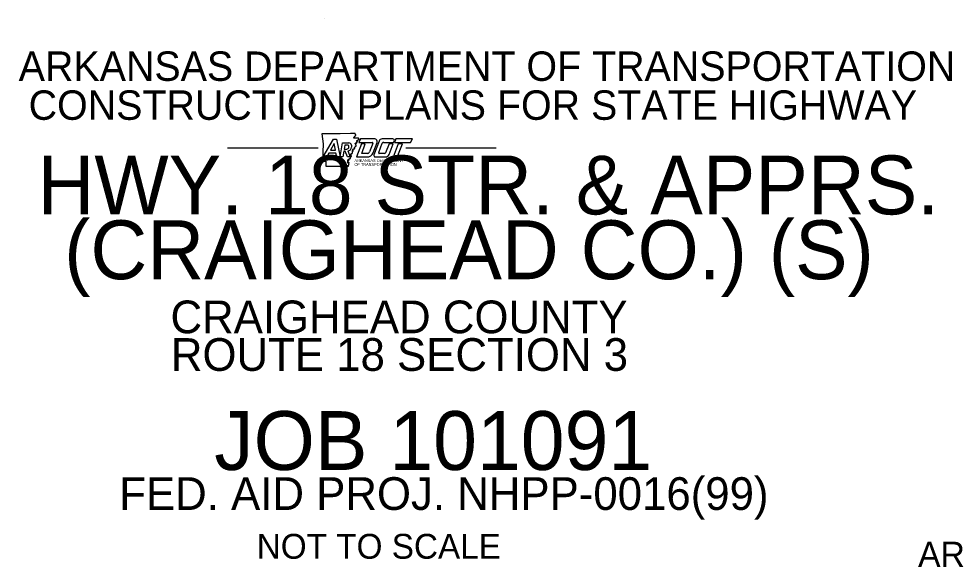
# Model space of a CAD drawing. Extents: x -28335 to 1228743, y -22428 to 152440.
# Drawn here: x -5314 to 23831, y 4514 to 21584 of the extents above; entities that cross this region are included whole.
import ezdxf

# ---------------------------------------------------------------- set-up
doc = ezdxf.new("R2010")
doc.units = 0
for name, color, linetype in [('2', 7, 'Continuous'), ('20', 7, 'Continuous'), ('58', 7, 'Continuous'), ('8', 7, 'Continuous'), ('Default', 7, 'Continuous')]:
    doc.layers.add(name, color=color, linetype=linetype)

msp = doc.modelspace()

# ---------------------------------------------------------------- linework, layer by layer
at = {"layer": '2'}
msp.add_line((4189, 21584), (4189, 21584), dxfattribs=at)
msp.add_line((4189, 21584), (4189, 21584), dxfattribs=at)
at = {"layer": '20'}
for p, q in [((4153, 17284), (4467, 17840)), ((4467, 17840), (4562, 17840)), ((4562, 17840), (4676, 17291)), ((5241, 17870), (5098, 17863)), ((5308, 17842), (5261, 17737)), ((5755, 17842), (5308, 17842)), ((6320, 17842), (5987, 17842)), ((6346, 17746), (6360, 17785)), ((6407, 17845), (6364, 17733)), ((6924, 17844), (6407, 17845)), ((6860, 17733), (6924, 17844)), ((4492, 17697), (4377, 17494)), ((4377, 17494), (4531, 17494)), ((4531, 17494), (4492, 17697)), ((4676, 17291), (4754, 17721)), ((4754, 17721), (4952, 17721)), ((4822, 17650), (4802, 17525)), ((4802, 17525), (4882, 17525)), ((4910, 17650), (4822, 17650)), ((4950, 17594), (4950, 17610)), ((5034, 17650), (5034, 17588)), ((5261, 17737), (5667, 17737)), ((5460, 17690), (5340, 17690)), ((5350, 17394), (5460, 17690)), ((5689, 17705), (5588, 17440)), ((5699, 17409), (5827, 17737)), ((5888, 17773), (5726, 17352)), ((5876, 17420), (5989, 17713)), ((6023, 17737), (6333, 17737)), ((6202, 17690), (6085, 17410)), ((6197, 17362), (6323, 17690)), ((6323, 17690), (6202, 17690)), ((6485, 17691), (6327, 17280)), ((6364, 17733), (6860, 17733)), ((6449, 17280), (6612, 17691)), ((6612, 17691), (6485, 17691)), ((4262, 17284), (4153, 17284)), ((4547, 17404), (4324, 17404)), ((4571, 17282), (4547, 17404)), ((4675, 17282), (4571, 17282)), ((4759, 17282), (4675, 17282)), ((4790, 17461), (4759, 17282)), ((4832, 17461), (4790, 17461)), ((4901, 17282), (4832, 17461)), ((4994, 17282), (4901, 17282)), ((4916, 17470), (4994, 17282)), ((5517, 17392), (5352, 17392)), ((5774, 17282), (6080, 17282)), ((6058, 17392), (5892, 17392)), ((6327, 17280), (6449, 17280))]:
    msp.add_line(p, q, dxfattribs=at)
for points in [[(5143, 18010), (4997, 18007), (4681, 18002), (4414, 18001), (4110, 18002)], [(4110, 18002), (4149, 17688), (4132, 17177)], [(5340, 17690), (5183, 17282), (5515, 17282)], [(4324, 17404), (4262, 17284), (4262, 17283), (4262, 17284)], [(4236, 17147), (4236, 16995), (4926, 16993)]]:
    msp.add_lwpolyline(points, dxfattribs=at)
for centre, radius, start, end in [((5755, 17765), 77, 338.81, 90.0244), ((5987, 17735), 107, 90.0159, 159.0252), ((6320, 17799), 42.5, 339.9797, 90.0159), ((4882, 17593), 68.4, 270, 0.8203), ((4910, 17610), 40, 0, 90.2531), ((4906, 17598), 128, 274.233, 355.6275), ((4942, 17627), 94.7, 14.1904, 83.9934), ((5667, 17714), 23.5, 339.1692, 89.9954), ((6023, 17700), 37.2, 90.0183, 159.0781), ((6333, 17750), 13.1, 270.0183, 339.9797), ((5352, 17394), 1.77, 159.6445, 270.0081), ((5515, 17480), 198, 269.9471, 338.81), ((5517, 17467), 75.1, 270.0081, 339.1692), ((5774, 17334), 51.6, 159.0252, 269.9823), ((5891, 17410), 18, 146.4856, 270.228), ((6058, 17421), 29.4, 270.0618, 337.3322), ((6080, 17407), 125, 269.9823, 339.0187)]:
    msp.add_arc(centre, radius, start, end, dxfattribs=at)
for points in [[(5098, 17863), (5103, 17875), (5104, 17880), (5108, 17886), (5110, 17891), (5115, 17896), (5118, 17900), (5122, 17904), (5124, 17910), (5128, 17915), (5132, 17919), (5137, 17924), (5142, 17929), (5145, 17933), (5149, 17937), (5153, 17940), (5158, 17945), (5159, 17951), (5160, 17957), (5160, 17964), (5161, 17971), (5160, 17977), (5156, 17983), (5150, 17986), (5147, 17990), (5146, 17998), (5144, 18002), (5143, 18010)], [(5065, 17452), (5064, 17453), (5059, 17458), (5059, 17466), (5059, 17472), (5060, 17478), (5063, 17482), (5066, 17478), (5068, 17474), (5069, 17469), (5073, 17467), (5078, 17468), (5081, 17473), (5083, 17478), (5083, 17483), (5081, 17487), (5076, 17488), (5070, 17489), (5067, 17492), (5069, 17500), (5069, 17505), (5069, 17511), (5073, 17513), (5075, 17510), (5074, 17505), (5074, 17500), (5081, 17497), (5085, 17502)], [(5085, 17502), (5086, 17511), (5087, 17516), (5086, 17525), (5084, 17531), (5084, 17537), (5088, 17539), (5092, 17538), (5096, 17535), (5100, 17530), (5104, 17529), (5108, 17531), (5112, 17531), (5117, 17531), (5121, 17530), (5124, 17532), (5126, 17536), (5127, 17542), (5131, 17545), (5133, 17550), (5134, 17556), (5133, 17561), (5130, 17567), (5126, 17572), (5126, 17579), (5129, 17583), (5135, 17584), (5136, 17585)], [(5136, 17585), (5141, 17585), (5145, 17591), (5147, 17596), (5149, 17600), (5152, 17606), (5154, 17611), (5158, 17615), (5163, 17614), (5168, 17613), (5172, 17614), (5175, 17620), (5174, 17625), (5172, 17631), (5171, 17636), (5170, 17644), (5167, 17647), (5161, 17650), (5156, 17655), (5152, 17659), (5158, 17663), (5164, 17666), (5163, 17672), (5164, 17678), (5168, 17684), (5167, 17689)], [(4915, 17188), (4917, 17192), (4921, 17193), (4927, 17191), (4933, 17188), (4938, 17184), (4945, 17181), (4950, 17184), (4954, 17189), (4952, 17196), (4946, 17197), (4941, 17197), (4935, 17203), (4935, 17212), (4939, 17213), (4945, 17216), (4949, 17217), (4954, 17215), (4961, 17213), (4964, 17215), (4969, 17222), (4970, 17228), (4971, 17233), (4986, 17232), (4995, 17237), (4995, 17247), (4996, 17254)], [(4996, 17254), (4998, 17260), (4998, 17265), (4999, 17267), (5000, 17272), (5005, 17274), (5011, 17282), (5012, 17294), (5030, 17299), (5031, 17307), (5032, 17313), (5026, 17320), (5019, 17323), (5012, 17338), (5013, 17353), (5008, 17362), (5012, 17364), (5013, 17364)], [(5013, 17364), (5018, 17364), (5024, 17368), (5024, 17369), (5025, 17375), (5024, 17380), (5022, 17387), (5023, 17390), (5027, 17390), (5032, 17388), (5033, 17385), (5033, 17382), (5034, 17379), (5036, 17377), (5039, 17377), (5043, 17382), (5044, 17386), (5045, 17392), (5048, 17395), (5051, 17397), (5056, 17402), (5058, 17407), (5060, 17415), (5059, 17423), (5061, 17430), (5062, 17436), (5066, 17442), (5067, 17447), (5065, 17452)], [(4132, 17177), (4137, 17170), (4139, 17165), (4143, 17159), (4147, 17156), (4153, 17155), (4154, 17149), (4159, 17148), (4164, 17150), (4170, 17148), (4177, 17152), (4181, 17151), (4186, 17154), (4190, 17150), (4197, 17153), (4204, 17157), (4210, 17153), (4216, 17153), (4222, 17152), (4228, 17152), (4233, 17149), (4236, 17147)], [(4947, 17117), (4946, 17116), (4943, 17113), (4941, 17110), (4938, 17107), (4936, 17104), (4931, 17102), (4924, 17101), (4921, 17103), (4920, 17108), (4924, 17112), (4929, 17114), (4933, 17116), (4936, 17121), (4934, 17127), (4929, 17130), (4925, 17127), (4923, 17123), (4921, 17120), (4917, 17118), (4914, 17117), (4912, 17119), (4912, 17124), (4915, 17131), (4917, 17136), (4917, 17141), (4915, 17149), (4913, 17155), (4914, 17156), (4918, 17158), (4924, 17160), (4927, 17161), (4928, 17166), (4924, 17172), (4919, 17177), (4916, 17184), (4915, 17188)], [(4926, 16993), (4934, 16997), (4937, 17001), (4937, 17004), (4935, 17009), (4931, 17014), (4928, 17016), (4924, 17021), (4923, 17027), (4927, 17030), (4934, 17029), (4941, 17029), (4944, 17031), (4945, 17036), (4945, 17040), (4945, 17045), (4947, 17052), (4950, 17057), (4954, 17062), (4954, 17067), (4951, 17070), (4946, 17069), (4942, 17068), (4939, 17073), (4937, 17078), (4936, 17086), (4941, 17093), (4945, 17097), (4949, 17102), (4951, 17108), (4952, 17114), (4950, 17117), (4947, 17117)]]:
    msp.add_spline(points, degree=3, dxfattribs=at)
for points in [[(5199, 17777), (5199, 17777), (5199, 17777), (5199, 17778), (5199, 17778), (5200, 17779), (5200, 17780), (5200, 17780), (5200, 17781), (5200, 17781), (5200, 17782), (5200, 17783), (5200, 17783), (5200, 17784), (5199, 17784), (5199, 17785), (5199, 17785), (5199, 17786), (5199, 17787), (5199, 17787), (5199, 17788), (5199, 17788), (5199, 17789), (5199, 17789), (5199, 17790), (5199, 17790), (5200, 17791), (5200, 17791), (5200, 17792), (5201, 17793), (5202, 17793), (5202, 17794), (5202, 17794), (5202, 17794), (5202, 17794), (5203, 17794), (5203, 17794), (5203, 17795), (5204, 17795), (5204, 17795), (5205, 17795), (5205, 17796), (5206, 17796), (5206, 17796), (5207, 17796), (5208, 17796), (5209, 17796), (5209, 17797), (5210, 17797), (5211, 17797), (5212, 17797), (5213, 17797), (5214, 17797), (5214, 17797), (5215, 17797), (5215, 17797), (5216, 17797), (5216, 17797), (5217, 17798), (5217, 17798), (5217, 17798), (5218, 17798), (5218, 17798), (5219, 17798), (5220, 17798), (5221, 17798), (5222, 17799), (5223, 17799), (5224, 17799), (5225, 17800), (5226, 17800), (5227, 17800), (5228, 17800), (5229, 17801), (5230, 17801), (5231, 17801), (5231, 17802), (5231, 17802), (5231, 17802), (5232, 17803), (5232, 17803), (5232, 17803), (5232, 17804), (5232, 17804), (5232, 17805), (5233, 17805), (5233, 17805), (5233, 17806), (5233, 17806), (5234, 17806), (5234, 17807)], [(5234, 17807), (5234, 17807), (5234, 17807), (5234, 17807), (5235, 17807), (5235, 17808), (5235, 17808), (5236, 17809), (5236, 17809), (5237, 17809), (5237, 17810), (5238, 17810), (5238, 17810), (5239, 17811), (5239, 17811), (5240, 17811), (5240, 17811), (5241, 17811), (5241, 17811), (5242, 17812), (5242, 17812), (5243, 17812), (5243, 17812), (5244, 17812), (5244, 17812), (5245, 17813), (5246, 17813), (5247, 17814), (5248, 17814), (5249, 17815), (5250, 17815), (5251, 17815), (5251, 17816), (5251, 17816), (5252, 17817), (5252, 17817), (5252, 17817), (5253, 17818), (5253, 17819), (5253, 17820), (5253, 17820), (5253, 17821), (5253, 17821), (5253, 17822), (5253, 17822), (5253, 17823), (5253, 17823), (5253, 17824), (5253, 17824), (5252, 17824), (5252, 17825), (5252, 17825), (5251, 17826), (5251, 17826), (5250, 17827), (5250, 17827), (5250, 17827), (5249, 17828), (5249, 17828), (5248, 17828), (5248, 17829), (5247, 17829), (5247, 17829), (5246, 17830), (5245, 17831), (5245, 17832), (5244, 17832), (5243, 17833), (5243, 17833), (5243, 17834), (5242, 17834), (5242, 17834), (5242, 17835), (5242, 17835), (5242, 17835), (5242, 17835), (5242, 17835), (5242, 17835), (5242, 17835), (5242, 17836), (5242, 17836), (5242, 17836), (5243, 17836), (5243, 17837), (5244, 17837), (5244, 17837), (5245, 17838), (5245, 17838), (5246, 17838), (5246, 17838), (5247, 17839), (5247, 17839), (5247, 17839), (5247, 17839), (5248, 17839), (5248, 17839), (5248, 17839), (5249, 17839), (5249, 17839), (5250, 17839), (5250, 17839), (5250, 17839), (5251, 17838), (5251, 17838), (5251, 17838), (5251, 17838)], [(5251, 17838), (5251, 17838), (5252, 17838), (5252, 17838), (5253, 17839), (5254, 17839), (5255, 17839), (5256, 17839), (5257, 17839), (5258, 17839), (5258, 17839), (5259, 17839), (5259, 17839), (5259, 17839), (5259, 17839), (5259, 17839), (5260, 17839), (5260, 17839), (5261, 17839), (5261, 17839), (5262, 17839), (5262, 17839), (5263, 17839), (5263, 17840), (5263, 17840), (5264, 17840), (5264, 17840), (5264, 17840), (5264, 17840), (5264, 17840), (5264, 17840), (5264, 17840), (5264, 17841), (5264, 17841), (5264, 17841), (5265, 17841), (5265, 17842), (5265, 17842), (5265, 17842), (5265, 17843), (5265, 17843), (5265, 17844), (5265, 17844), (5264, 17846), (5263, 17847), (5262, 17849), (5261, 17850), (5260, 17852), (5259, 17853), (5258, 17853), (5258, 17854), (5258, 17854), (5257, 17854), (5257, 17854), (5256, 17854), (5256, 17854), (5255, 17854), (5255, 17854), (5255, 17854), (5254, 17854), (5254, 17855), (5252, 17855), (5251, 17856), (5250, 17858), (5250, 17858), (5249, 17859), (5249, 17859), (5249, 17860), (5249, 17860), (5248, 17861), (5248, 17861), (5248, 17862), (5248, 17862), (5247, 17863), (5247, 17863), (5247, 17864), (5247, 17864), (5246, 17864), (5246, 17865), (5246, 17865), (5246, 17865), (5246, 17866), (5245, 17866), (5245, 17867), (5244, 17868), (5244, 17868), (5243, 17869), (5243, 17869), (5242, 17870), (5241, 17870), (5241, 17870)], [(5167, 17689), (5166, 17690), (5166, 17691), (5166, 17692), (5165, 17693), (5165, 17693), (5165, 17693), (5165, 17694), (5164, 17694), (5164, 17694), (5164, 17694), (5164, 17695), (5164, 17695), (5164, 17695), (5163, 17695), (5163, 17695), (5163, 17695), (5162, 17695), (5162, 17695), (5162, 17695), (5162, 17695), (5161, 17695), (5161, 17695), (5161, 17695), (5161, 17694), (5160, 17694), (5160, 17694), (5160, 17693), (5160, 17693), (5160, 17693), (5160, 17692), (5160, 17692), (5160, 17692), (5160, 17691), (5159, 17691), (5159, 17691), (5159, 17690), (5159, 17690), (5158, 17690), (5158, 17690), (5158, 17690), (5158, 17690), (5157, 17690), (5157, 17689), (5157, 17689), (5157, 17689), (5156, 17689), (5156, 17689), (5156, 17689), (5155, 17689), (5155, 17689), (5155, 17689), (5154, 17689), (5154, 17689), (5154, 17690), (5153, 17690), (5153, 17690), (5153, 17690), (5152, 17690), (5152, 17690), (5152, 17691), (5151, 17691), (5151, 17691), (5151, 17691), (5151, 17691), (5151, 17691), (5151, 17691), (5151, 17692), (5151, 17692), (5150, 17692), (5150, 17693), (5150, 17693), (5150, 17694), (5149, 17694), (5149, 17695), (5149, 17695), (5149, 17696), (5150, 17696), (5150, 17697), (5150, 17697), (5150, 17697), (5150, 17698), (5151, 17698), (5151, 17699), (5151, 17699), (5152, 17700), (5152, 17701), (5153, 17701), (5153, 17702), (5154, 17702), (5154, 17703), (5155, 17703), (5155, 17703), (5156, 17704), (5156, 17704), (5157, 17705), (5157, 17705), (5158, 17705), (5158, 17706), (5159, 17706), (5159, 17707), (5160, 17707), (5161, 17708), (5161, 17709), (5162, 17710), (5163, 17710), (5163, 17711), (5164, 17711), (5165, 17712), (5165, 17712), (5165, 17712), (5166, 17713), (5166, 17713), (5166, 17713), (5167, 17713), (5167, 17714), (5168, 17714), (5168, 17714)], [(5168, 17714), (5168, 17714), (5168, 17714), (5168, 17714), (5169, 17714), (5169, 17713), (5170, 17713), (5170, 17713), (5170, 17713), (5171, 17712), (5171, 17712), (5171, 17712), (5171, 17711), (5172, 17711), (5172, 17711), (5172, 17711), (5172, 17710), (5172, 17710), (5172, 17710), (5172, 17709), (5172, 17709), (5172, 17708), (5172, 17708), (5172, 17707), (5173, 17707), (5173, 17706), (5173, 17705), (5173, 17704), (5173, 17703), (5173, 17701), (5173, 17700), (5174, 17699), (5174, 17698), (5174, 17697), (5174, 17696), (5174, 17696), (5175, 17696), (5175, 17696), (5175, 17696), (5175, 17696), (5175, 17696), (5176, 17696), (5176, 17697), (5177, 17697), (5178, 17698), (5178, 17699), (5178, 17699), (5179, 17700), (5179, 17700), (5179, 17701), (5180, 17701), (5180, 17702), (5180, 17702), (5180, 17703), (5181, 17704), (5181, 17704), (5181, 17705), (5181, 17705), (5182, 17707), (5182, 17710), (5183, 17712), (5183, 17713), (5183, 17715), (5183, 17716), (5182, 17718), (5182, 17720), (5181, 17722), (5181, 17724), (5180, 17725), (5180, 17727), (5180, 17727), (5180, 17727), (5180, 17727)], [(5180, 17727), (5180, 17728), (5180, 17728), (5180, 17728), (5180, 17729), (5180, 17729), (5180, 17730), (5181, 17730), (5181, 17731), (5181, 17731), (5181, 17732), (5181, 17732), (5182, 17732), (5182, 17733), (5182, 17733), (5182, 17733), (5182, 17733), (5182, 17734), (5181, 17734), (5181, 17734), (5181, 17735), (5181, 17735), (5181, 17736), (5181, 17736), (5181, 17737), (5181, 17737), (5181, 17737), (5182, 17738), (5182, 17738), (5182, 17738), (5182, 17738), (5182, 17739), (5182, 17739), (5182, 17739), (5183, 17739), (5183, 17740), (5183, 17740), (5184, 17740), (5184, 17740), (5185, 17740), (5185, 17740), (5185, 17740), (5186, 17740), (5187, 17740), (5188, 17739), (5189, 17739), (5191, 17738), (5192, 17738), (5193, 17737), (5194, 17737), (5194, 17737), (5194, 17736), (5195, 17736), (5195, 17735), (5195, 17735), (5195, 17734), (5196, 17734), (5196, 17733), (5196, 17733), (5196, 17733), (5197, 17732), (5198, 17732), (5198, 17732), (5199, 17731), (5200, 17731), (5201, 17731), (5202, 17731), (5203, 17732), (5204, 17732), (5204, 17732), (5205, 17733), (5205, 17733), (5205, 17733), (5206, 17733), (5206, 17733), (5206, 17734), (5206, 17734), (5206, 17734), (5206, 17734), (5207, 17735), (5207, 17737), (5207, 17738), (5206, 17740), (5205, 17741), (5204, 17742), (5204, 17743), (5203, 17743), (5203, 17743), (5203, 17743), (5202, 17744), (5202, 17744), (5202, 17744), (5201, 17744), (5201, 17744), (5201, 17745), (5200, 17745), (5200, 17745)], [(5200, 17745), (5200, 17745), (5200, 17745), (5200, 17745), (5199, 17746), (5199, 17746), (5198, 17747), (5198, 17748), (5198, 17749), (5198, 17749), (5199, 17749), (5199, 17750), (5199, 17750), (5200, 17751), (5200, 17751), (5200, 17751), (5201, 17752), (5202, 17753), (5203, 17753), (5203, 17753), (5204, 17753), (5204, 17754), (5204, 17754), (5205, 17754), (5205, 17754), (5206, 17754), (5206, 17754), (5206, 17754), (5207, 17755), (5207, 17755), (5208, 17755), (5209, 17756), (5211, 17758), (5212, 17759), (5213, 17760), (5213, 17760), (5213, 17760), (5214, 17761), (5214, 17761), (5214, 17762), (5215, 17763), (5216, 17763), (5216, 17764), (5217, 17765), (5217, 17766), (5217, 17766), (5217, 17767), (5217, 17767), (5217, 17768), (5217, 17768), (5217, 17768), (5217, 17769), (5217, 17769), (5216, 17769), (5216, 17769), (5216, 17769), (5216, 17770), (5216, 17770), (5215, 17770), (5215, 17770), (5214, 17770), (5213, 17771), (5212, 17771), (5211, 17771), (5211, 17772), (5210, 17772), (5210, 17772), (5210, 17772), (5209, 17772), (5209, 17772), (5208, 17772), (5208, 17772), (5207, 17772), (5207, 17772), (5206, 17772), (5206, 17772), (5205, 17772), (5205, 17772), (5204, 17772), (5204, 17772), (5203, 17772), (5202, 17772), (5202, 17772), (5201, 17773), (5201, 17773), (5200, 17773), (5200, 17774), (5200, 17774), (5200, 17774), (5200, 17774), (5199, 17775), (5199, 17775), (5199, 17775), (5199, 17775), (5199, 17775), (5199, 17776), (5199, 17776), (5199, 17776), (5199, 17776), (5199, 17777)]]:
    msp.add_open_spline(points, degree=3, dxfattribs=at)
at = {"layer": '8'}
for p, q in [((1178, 17562), (3993, 17562)), ((6715, 17562), (9530, 17562))]:
    msp.add_line(p, q, dxfattribs=at)

# ---------------------------------------------------------------- texts
at = {"layer": '20'}
for s, height, p in [('ARKANSAS', 87.2, (5122, 17126)), ('DEPARTMENT', 87.2, (5819, 17126)), ('OF TRANSPORTATION', 87.23, (5122, 17005))]:
    msp.add_text(s, height=height, dxfattribs=at).set_placement(p)
at = {"layer": '58'}
msp.add_text('NOT TO SCALE', height=774.01, dxfattribs=at).set_placement((2084, 4779))
at = {"layer": '8'}
for s, height, p in [('ARKANSAS DEPARTMENT OF TRANSPORTATION', 915.67, (-5316, 19650)), ('CONSTRUCTION PLANS FOR STATE HIGHWAY', 915.67, (-5007, 18438)), ('ARKANSAS HIGHWAY DISTRICT 10', 783.39, (22644, 4525))]:
    msp.add_text(s, height=height, dxfattribs=at).set_placement(p)
at = {"layer": 'Default'}
for s, height, p in [('HWY. 18 STR. & APPRS. ', 1831.35, (-4733, 15495)), ('(CRAIGHEAD CO.) (S)', 1831.35, (-3902, 13478)), ('CRAIGHEAD COUNTY', 1017.41, (-597, 11796)), ('ROUTE 18 SECTION 3', 1017.41, (-585, 10626)), ('JOB 101091', 1831.3, (764, 7541)), ('FED. AID PROJ. NHPP-0016(99)', 1017.41, (-2191, 6298))]:
    msp.add_text(s, height=height, dxfattribs=at).set_placement(p)

doc.saveas('drawing.dxf')
